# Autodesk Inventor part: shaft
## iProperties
Created: 2005-11
Part Number: shaft
Document SubType Name: Modeling
Designer: Paul
Material: Titanium
Author: Paul
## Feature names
1. Revolution1
2. Chamfer1
